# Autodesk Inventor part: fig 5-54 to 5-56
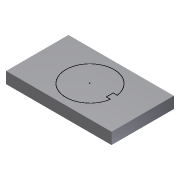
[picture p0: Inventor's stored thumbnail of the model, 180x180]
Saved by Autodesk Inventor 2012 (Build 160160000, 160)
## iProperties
Created: 2005-12
Part Number: fig 5-54 to 5-56
Document SubType Name: Modeling
Designer: CADCIM
Density: 1 g/cm^3
Material: Default
Author: CADCIM
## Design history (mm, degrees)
sketch "Sketch1"
  geometry: L1 (-47.674, -20.831)-(44.057, -20.831); L2 (44.057, -20.831)-(44.057, 33.398); L3 (44.057, 33.398)-(-47.674, 33.398); L4 (-47.674, 33.398)-(-47.674, -20.831)
  constraints: 8 end point, 2 parallel, 1 horizontal, 1 perpendicular
extrude "Extrusion1" new body sketch "Sketch1" distance "d0" = 10; taper "d1" = 0 deg
sketch "Sketch2"
  geometry: L1 (15.359, 9.199)-(18.885, 9.199); L2 (18.885, 3.199)-(15.359, 3.199); L3 (15.359, 3.199)-(15.359, 9.199); A1 r 20.978 centre (-1.877, 6.199) between (18.885, 9.199) and (18.885, 3.199)
  constraints: 6 end point, 2 parallel, 2 point on circle, 1 centre point, 1 horizontal, 1 vertical
body "Solid1"
